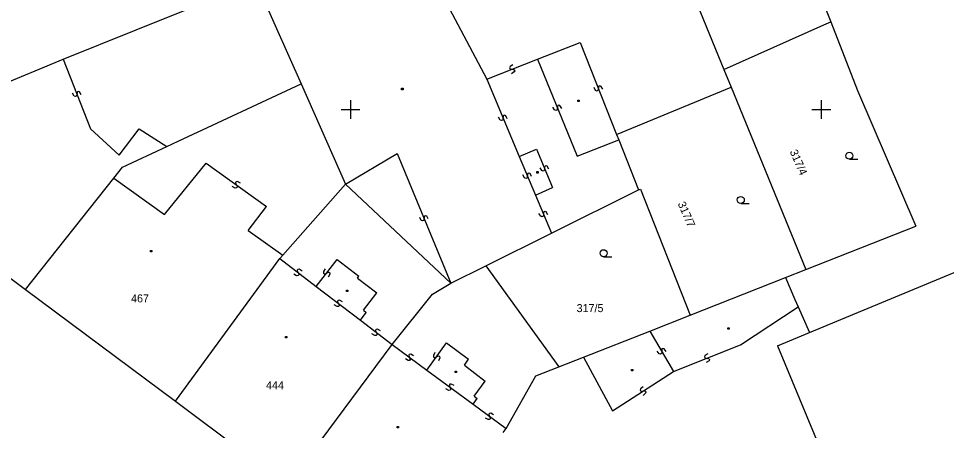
# Model space of a CAD drawing. Extents: x -492379 to -491966, y -1126153 to -1125860.
# Drawn here: x -492201.2 to -492142, y -1125920.5 to -1125894.2 of the extents above; entities that cross this region are included whole.
import ezdxf

# ---------------------------------------------------------------- set-up
doc = ezdxf.new("R2010")
doc.units = 0
doc.layers.add('katastrální mapa', color=7, linetype='Continuous')
doc.layers.add('síť', color=7, linetype='Continuous')

msp = doc.modelspace()

# ---------------------------------------------------------------- linework, layer by layer
at = {"layer": 'katastrální mapa'}
for p, q in [((-492176.64, -1125888.01), (-492171.32, -1125898.08)), ((-492150.75, -1125914.23), (-492091.06, -1125889.38)), ((-492150.62, -1125891.29), (-492149.4, -1125894.41)), ((-492193.65, -1125894.92), (-492186.04, -1125891.85)), ((-492186.04, -1125891.85), (-492183.14, -1125898.37)), ((-492158.08, -1125892.87), (-492156.21, -1125897.45)), ((-492156.21, -1125897.45), (-492149.83, -1125894.6)), ((-492149.83, -1125894.6), (-492149.4, -1125894.41)), ((-492149.4, -1125894.41), (-492147.69, -1125898.79)), ((-492198.3, -1125896.79), (-492193.65, -1125894.92)), ((-492168.08, -1125896.8), (-492165.36, -1125895.73)), ((-492165.36, -1125895.73), (-492163.05, -1125901.59)), ((-492209.37, -1125901.37), (-492198.3, -1125896.79)), ((-492198.3, -1125896.79), (-492196.56, -1125901.24)), ((-492171.32, -1125898.08), (-492168.08, -1125896.8)), ((-492169.83, -1125897.27), (-492169.87, -1125897.34)), ((-492169.65, -1125897.16), (-492169.83, -1125897.27)), ((-492168.08, -1125896.8), (-492165.56, -1125902.99)), ((-492169.87, -1125897.34), (-492169.84, -1125897.4)), ((-492169.84, -1125897.4), (-492169.77, -1125897.43)), ((-492169.77, -1125897.43), (-492169.63, -1125897.45)), ((-492169.57, -1125897.61), (-492169.75, -1125897.72)), ((-492169.63, -1125897.45), (-492169.56, -1125897.48)), ((-492169.53, -1125897.54), (-492169.57, -1125897.61)), ((-492169.56, -1125897.48), (-492169.53, -1125897.54)), ((-492156.21, -1125897.45), (-492155.74, -1125898.59)), ((-492190.98, -1125902.03), (-492183.14, -1125898.37)), ((-492183.14, -1125898.37), (-492180.31, -1125904.76)), ((-492171.32, -1125898.08), (-492169.25, -1125903)), ((-492197.6, -1125899.15), (-492197.71, -1125898.96)), ((-492197.42, -1125898.95), (-492197.44, -1125899.08)), ((-492197.39, -1125898.87), (-492197.42, -1125898.95)), ((-492197.33, -1125898.85), (-492197.39, -1125898.87)), ((-492197.26, -1125898.88), (-492197.33, -1125898.85)), ((-492197.15, -1125899.07), (-492197.26, -1125898.88)), ((-492176.74, -1125898.65), (-492176.65, -1125898.65)), ((-492176.74, -1125898.74), (-492176.74, -1125898.65)), ((-492176.65, -1125898.74), (-492176.74, -1125898.74)), ((-492176.65, -1125898.65), (-492176.65, -1125898.74)), ((-492164.38, -1125898.79), (-492164.48, -1125898.61)), ((-492164.3, -1125898.83), (-492164.38, -1125898.79)), ((-492164.24, -1125898.8), (-492164.3, -1125898.83)), ((-492164.21, -1125898.73), (-492164.24, -1125898.8)), ((-492164.2, -1125898.59), (-492164.21, -1125898.73)), ((-492164.17, -1125898.52), (-492164.2, -1125898.59)), ((-492164.11, -1125898.49), (-492164.17, -1125898.52)), ((-492164.03, -1125898.53), (-492164.11, -1125898.49)), ((-492163.93, -1125898.71), (-492164.03, -1125898.53)), ((-492163.05, -1125901.59), (-492155.74, -1125898.59)), ((-492155.74, -1125898.59), (-492150.99, -1125910.22)), ((-492147.69, -1125898.79), (-492143.97, -1125907.45)), ((-492197.53, -1125899.18), (-492197.6, -1125899.15)), ((-492197.47, -1125899.16), (-492197.53, -1125899.18)), ((-492197.44, -1125899.08), (-492197.47, -1125899.16)), ((-492165.52, -1125899.41), (-492165.43, -1125899.41)), ((-492165.52, -1125899.5), (-492165.52, -1125899.41)), ((-492165.43, -1125899.5), (-492165.52, -1125899.5)), ((-492165.43, -1125899.41), (-492165.43, -1125899.5)), ((-492166.99, -1125900.03), (-492167.1, -1125899.85)), ((-492166.91, -1125900.06), (-492166.99, -1125900.03)), ((-492166.86, -1125900.04), (-492166.91, -1125900.06)), ((-492166.83, -1125899.96), (-492166.86, -1125900.04)), ((-492166.81, -1125899.83), (-492166.83, -1125899.96)), ((-492166.78, -1125899.75), (-492166.81, -1125899.83)), ((-492166.73, -1125899.73), (-492166.78, -1125899.75)), ((-492166.65, -1125899.76), (-492166.73, -1125899.73)), ((-492166.54, -1125899.94), (-492166.65, -1125899.76)), ((-492170.46, -1125900.68), (-492170.56, -1125900.49)), ((-492170.38, -1125900.71), (-492170.46, -1125900.68)), ((-492170.32, -1125900.69), (-492170.38, -1125900.71)), ((-492170.29, -1125900.61), (-492170.32, -1125900.69)), ((-492170.28, -1125900.47), (-492170.29, -1125900.61)), ((-492170.25, -1125900.39), (-492170.28, -1125900.47)), ((-492170.19, -1125900.37), (-492170.25, -1125900.39)), ((-492170.11, -1125900.4), (-492170.19, -1125900.37)), ((-492170.01, -1125900.59), (-492170.11, -1125900.4)), ((-492196.56, -1125901.24), (-492194.74, -1125902.92)), ((-492194.74, -1125902.92), (-492193.47, -1125901.24)), ((-492193.47, -1125901.24), (-492191.7, -1125902.37)), ((-492165.56, -1125902.99), (-492162.91, -1125901.94)), ((-492163.05, -1125901.59), (-492162.91, -1125901.94)), ((-492162.91, -1125901.94), (-492161.64, -1125905.14)), ((-492194.52, -1125903.69), (-492191.7, -1125902.37)), ((-492191.7, -1125902.37), (-492190.98, -1125902.03)), ((-492169.25, -1125903), (-492168.15, -1125902.54)), ((-492168.15, -1125902.54), (-492167.12, -1125904.99)), ((-492180.31, -1125904.76), (-492177.02, -1125902.81)), ((-492177.02, -1125902.81), (-492173.61, -1125911.08)), ((-492169.25, -1125903), (-492168.22, -1125905.46)), ((-492148.21, -1125903.18), (-492147.68, -1125903.18)), ((-492195.08, -1125904.39), (-492194.52, -1125903.69)), ((-492191.86, -1125906.71), (-492189.19, -1125903.43)), ((-492189.19, -1125903.43), (-492185.36, -1125906.19)), ((-492167.81, -1125903.9), (-492167.91, -1125903.72)), ((-492167.63, -1125903.7), (-492167.64, -1125903.83)), ((-492167.6, -1125903.62), (-492167.63, -1125903.7)), ((-492167.54, -1125903.6), (-492167.6, -1125903.62)), ((-492167.46, -1125903.63), (-492167.54, -1125903.6)), ((-492167.36, -1125903.81), (-492167.46, -1125903.63)), ((-492168.91, -1125904.37), (-492169.01, -1125904.18)), ((-492168.74, -1125904.3), (-492168.77, -1125904.38)), ((-492168.73, -1125904.16), (-492168.74, -1125904.3)), ((-492168.7, -1125904.08), (-492168.73, -1125904.16)), ((-492168.64, -1125904.06), (-492168.7, -1125904.08)), ((-492168.56, -1125904.09), (-492168.64, -1125904.06)), ((-492168.46, -1125904.28), (-492168.56, -1125904.09)), ((-492168.13, -1125903.97), (-492168.04, -1125903.97)), ((-492168.13, -1125904.06), (-492168.13, -1125903.97)), ((-492168.04, -1125904.06), (-492168.13, -1125904.06)), ((-492168.04, -1125903.97), (-492168.04, -1125904.06)), ((-492167.73, -1125903.93), (-492167.81, -1125903.9)), ((-492167.67, -1125903.91), (-492167.73, -1125903.93)), ((-492167.64, -1125903.83), (-492167.67, -1125903.91)), ((-492209.77, -1125904.73), (-492200.7, -1125911.49)), ((-492200.7, -1125911.49), (-492195.08, -1125904.39)), ((-492195.08, -1125904.39), (-492191.86, -1125906.71)), ((-492187.35, -1125905.02), (-492187.54, -1125904.92)), ((-492187.28, -1125904.62), (-492187.32, -1125904.67)), ((-492187.32, -1125904.67), (-492187.31, -1125904.75)), ((-492187.31, -1125904.75), (-492187.24, -1125904.87)), ((-492187.2, -1125904.6), (-492187.28, -1125904.62)), ((-492187.23, -1125904.95), (-492187.27, -1125905)), ((-492187.24, -1125904.87), (-492187.23, -1125904.95)), ((-492187.01, -1125904.7), (-492187.2, -1125904.6)), ((-492184.31, -1125909.3), (-492180.31, -1125904.76)), ((-492180.31, -1125904.76), (-492173.61, -1125911.08)), ((-492168.83, -1125904.4), (-492168.91, -1125904.37)), ((-492168.77, -1125904.38), (-492168.83, -1125904.4)), ((-492187.27, -1125905), (-492187.35, -1125905.02)), ((-492168.22, -1125905.46), (-492167.12, -1125904.99)), ((-492168.22, -1125905.46), (-492167.2, -1125907.9)), ((-492167.2, -1125907.9), (-492161.64, -1125905.14)), ((-492161.64, -1125905.14), (-492161.53, -1125905.08)), ((-492161.53, -1125905.08), (-492158.36, -1125913.13)), ((-492155.13, -1125906), (-492154.6, -1125906)), ((-492186.51, -1125907.72), (-492185.36, -1125906.19)), ((-492167.88, -1125906.82), (-492167.99, -1125906.63)), ((-492167.67, -1125906.53), (-492167.71, -1125906.61)), ((-492167.71, -1125906.61), (-492167.71, -1125906.75)), ((-492167.62, -1125906.51), (-492167.67, -1125906.53)), ((-492167.54, -1125906.54), (-492167.62, -1125906.51)), ((-492167.43, -1125906.73), (-492167.54, -1125906.54)), ((-492175.49, -1125907.08), (-492175.59, -1125906.9)), ((-492175.41, -1125907.11), (-492175.49, -1125907.08)), ((-492175.35, -1125907.09), (-492175.41, -1125907.11)), ((-492175.32, -1125907.01), (-492175.35, -1125907.09)), ((-492175.31, -1125906.88), (-492175.32, -1125907.01)), ((-492175.28, -1125906.8), (-492175.31, -1125906.88)), ((-492175.22, -1125906.78), (-492175.28, -1125906.8)), ((-492175.14, -1125906.81), (-492175.22, -1125906.78)), ((-492175.04, -1125906.99), (-492175.14, -1125906.81)), ((-492167.8, -1125906.85), (-492167.88, -1125906.82)), ((-492167.75, -1125906.83), (-492167.8, -1125906.85)), ((-492167.71, -1125906.75), (-492167.75, -1125906.83)), ((-492186.51, -1125907.72), (-492184.31, -1125909.3)), ((-492171.37, -1125909.97), (-492167.2, -1125907.9)), ((-492150.99, -1125910.22), (-492143.97, -1125907.45)), ((-492192.75, -1125908.99), (-492192.66, -1125908.99)), ((-492192.75, -1125909.08), (-492192.75, -1125908.99)), ((-492192.66, -1125909.08), (-492192.75, -1125909.08)), ((-492192.66, -1125908.99), (-492192.66, -1125909.08)), ((-492191.15, -1125918.62), (-492184.51, -1125909.51)), ((-492184.51, -1125909.51), (-492184.31, -1125909.3)), ((-492184.51, -1125909.51), (-492182.18, -1125911.3)), ((-492182.18, -1125911.3), (-492180.85, -1125909.57)), ((-492180.85, -1125909.57), (-492179.46, -1125910.64)), ((-492163.87, -1125909.4), (-492163.34, -1125909.4)), ((-492183.35, -1125910.21), (-492183.39, -1125910.26)), ((-492183.39, -1125910.26), (-492183.37, -1125910.34)), ((-492183.26, -1125910.2), (-492183.35, -1125910.21)), ((-492183.08, -1125910.31), (-492183.26, -1125910.2)), ((-492181.61, -1125910.17), (-492181.72, -1125910.35)), ((-492173.61, -1125911.08), (-492171.37, -1125909.97)), ((-492171.37, -1125909.97), (-492166.72, -1125916.42)), ((-492152.29, -1125910.73), (-492150.99, -1125910.22)), ((-492183.43, -1125910.61), (-492183.61, -1125910.5)), ((-492183.34, -1125910.6), (-492183.43, -1125910.61)), ((-492183.37, -1125910.34), (-492183.32, -1125910.47)), ((-492183.3, -1125910.55), (-492183.34, -1125910.6)), ((-492183.32, -1125910.47), (-492183.3, -1125910.55)), ((-492181.72, -1125910.35), (-492181.71, -1125910.44)), ((-492181.71, -1125910.44), (-492181.66, -1125910.48)), ((-492181.66, -1125910.48), (-492181.58, -1125910.46)), ((-492181.58, -1125910.46), (-492181.45, -1125910.41)), ((-492181.45, -1125910.41), (-492181.37, -1125910.39)), ((-492181.31, -1125910.52), (-492181.42, -1125910.7)), ((-492181.37, -1125910.39), (-492181.32, -1125910.43)), ((-492181.32, -1125910.43), (-492181.31, -1125910.52)), ((-492179.56, -1125910.76), (-492179.46, -1125910.64)), ((-492179.56, -1125910.76), (-492178.32, -1125911.71)), ((-492158.36, -1125913.13), (-492152.29, -1125910.73)), ((-492152.29, -1125910.73), (-492151.68, -1125912.13)), ((-492182.18, -1125911.3), (-492179.37, -1125913.45)), ((-492174.78, -1125911.79), (-492173.61, -1125911.08)), ((-492200.7, -1125911.49), (-492191.15, -1125918.62)), ((-492180.25, -1125911.52), (-492180.16, -1125911.52)), ((-492180.25, -1125911.61), (-492180.25, -1125911.52)), ((-492180.16, -1125911.61), (-492180.25, -1125911.61)), ((-492180.16, -1125911.52), (-492180.16, -1125911.61)), ((-492179.17, -1125912.81), (-492178.32, -1125911.71)), ((-492177.35, -1125915), (-492174.78, -1125911.79)), ((-492180.85, -1125912.58), (-492181.04, -1125912.47)), ((-492180.77, -1125912.57), (-492180.85, -1125912.58)), ((-492180.78, -1125912.18), (-492180.82, -1125912.23)), ((-492180.82, -1125912.23), (-492180.8, -1125912.31)), ((-492180.8, -1125912.31), (-492180.75, -1125912.44)), ((-492180.7, -1125912.17), (-492180.78, -1125912.18)), ((-492180.73, -1125912.52), (-492180.77, -1125912.57)), ((-492180.75, -1125912.44), (-492180.73, -1125912.52)), ((-492180.51, -1125912.28), (-492180.7, -1125912.17)), ((-492155.15, -1125915.02), (-492151.47, -1125912.59)), ((-492151.68, -1125912.13), (-492151.47, -1125912.59)), ((-492151.47, -1125912.59), (-492150.75, -1125914.23)), ((-492179.37, -1125913.45), (-492178.99, -1125912.95)), ((-492179.17, -1125912.81), (-492178.99, -1125912.95)), ((-492160.92, -1125914.14), (-492158.36, -1125913.13)), ((-492179.37, -1125913.45), (-492177.35, -1125915)), ((-492178.44, -1125914.43), (-492178.63, -1125914.32)), ((-492178.36, -1125914.03), (-492178.4, -1125914.08)), ((-492178.4, -1125914.08), (-492178.39, -1125914.16)), ((-492178.39, -1125914.16), (-492178.33, -1125914.29)), ((-492178.28, -1125914.02), (-492178.36, -1125914.03)), ((-492178.32, -1125914.37), (-492178.36, -1125914.42)), ((-492178.33, -1125914.29), (-492178.32, -1125914.37)), ((-492178.09, -1125914.13), (-492178.28, -1125914.02)), ((-492165.16, -1125915.81), (-492160.92, -1125914.14)), ((-492160.92, -1125914.14), (-492159.42, -1125916.72)), ((-492155.95, -1125913.93), (-492155.86, -1125913.93)), ((-492155.95, -1125914.02), (-492155.95, -1125913.93)), ((-492155.86, -1125914.02), (-492155.95, -1125914.02)), ((-492155.86, -1125913.93), (-492155.86, -1125914.02)), ((-492152.78, -1125915.08), (-492150.75, -1125914.23)), ((-492184.14, -1125914.49), (-492184.05, -1125914.49)), ((-492184.14, -1125914.58), (-492184.14, -1125914.49)), ((-492184.05, -1125914.58), (-492184.14, -1125914.58)), ((-492184.05, -1125914.49), (-492184.05, -1125914.58)), ((-492183.99, -1125923.95), (-492177.35, -1125915)), ((-492178.36, -1125914.42), (-492178.44, -1125914.43)), ((-492177.35, -1125915), (-492175.13, -1125916.64)), ((-492175.13, -1125916.64), (-492173.89, -1125914.9)), ((-492173.89, -1125914.9), (-492172.48, -1125915.93)), ((-492174.62, -1125915.51), (-492174.72, -1125915.7)), ((-492160.32, -1125915.59), (-492160.45, -1125915.42)), ((-492160.24, -1125915.61), (-492160.32, -1125915.59)), ((-492160.19, -1125915.58), (-492160.24, -1125915.61)), ((-492160.17, -1125915.5), (-492160.19, -1125915.58)), ((-492160.15, -1125915.28), (-492160.17, -1125915.36)), ((-492160.17, -1125915.36), (-492160.17, -1125915.5)), ((-492160.1, -1125915.25), (-492160.15, -1125915.28)), ((-492160.02, -1125915.27), (-492160.1, -1125915.25)), ((-492159.89, -1125915.44), (-492160.02, -1125915.27)), ((-492159.42, -1125916.72), (-492155.15, -1125915.02)), ((-492157.23, -1125915.59), (-492157.42, -1125915.7)), ((-492152.78, -1125915.08), (-492149.61, -1125922.76)), ((-492176.32, -1125916.02), (-492176.5, -1125915.92)), ((-492176.23, -1125916.01), (-492176.32, -1125916.02)), ((-492176.25, -1125915.63), (-492176.28, -1125915.68)), ((-492176.28, -1125915.68), (-492176.27, -1125915.76)), ((-492176.27, -1125915.76), (-492176.21, -1125915.88)), ((-492176.16, -1125915.62), (-492176.25, -1125915.63)), ((-492176.2, -1125915.96), (-492176.23, -1125916.01)), ((-492176.21, -1125915.88), (-492176.2, -1125915.96)), ((-492175.98, -1125915.72), (-492176.16, -1125915.62)), ((-492174.72, -1125915.7), (-492174.7, -1125915.78)), ((-492174.7, -1125915.78), (-492174.65, -1125915.82)), ((-492174.65, -1125915.82), (-492174.57, -1125915.8)), ((-492174.57, -1125915.8), (-492174.45, -1125915.74)), ((-492174.45, -1125915.74), (-492174.37, -1125915.72)), ((-492174.3, -1125915.84), (-492174.4, -1125916.03)), ((-492174.37, -1125915.72), (-492174.32, -1125915.76)), ((-492174.32, -1125915.76), (-492174.3, -1125915.84)), ((-492172.73, -1125916.32), (-492172.48, -1125915.93)), ((-492166.72, -1125916.42), (-492165.16, -1125915.81)), ((-492165.16, -1125915.81), (-492163.3, -1125919.22)), ((-492157.42, -1125915.7), (-492157.45, -1125915.78)), ((-492157.45, -1125915.78), (-492157.43, -1125915.83)), ((-492157.43, -1125915.83), (-492157.35, -1125915.86)), ((-492157.35, -1125915.86), (-492157.22, -1125915.88)), ((-492157.15, -1125916.04), (-492157.34, -1125916.15)), ((-492157.22, -1125915.88), (-492157.14, -1125915.91)), ((-492157.12, -1125915.96), (-492157.15, -1125916.04)), ((-492157.14, -1125915.91), (-492157.12, -1125915.96)), ((-492175.13, -1125916.64), (-492172.19, -1125918.81)), ((-492173.33, -1125916.69), (-492173.24, -1125916.69)), ((-492173.33, -1125916.78), (-492173.33, -1125916.69)), ((-492173.24, -1125916.78), (-492173.33, -1125916.78)), ((-492173.24, -1125916.69), (-492173.24, -1125916.78)), ((-492172.73, -1125916.32), (-492171.41, -1125917.33)), ((-492168.18, -1125917), (-492166.72, -1125916.42)), ((-492163.3, -1125919.22), (-492159.42, -1125916.72)), ((-492162.1, -1125916.59), (-492162.01, -1125916.59)), ((-492162.1, -1125916.68), (-492162.1, -1125916.59)), ((-492162.01, -1125916.68), (-492162.1, -1125916.68)), ((-492162.01, -1125916.59), (-492162.01, -1125916.68)), ((-492172.12, -1125918.29), (-492171.41, -1125917.33)), ((-492170.09, -1125920.36), (-492168.18, -1125917)), ((-492173.74, -1125917.93), (-492173.92, -1125917.83)), ((-492173.65, -1125917.92), (-492173.74, -1125917.93)), ((-492173.67, -1125917.53), (-492173.7, -1125917.58)), ((-492173.7, -1125917.58), (-492173.69, -1125917.67)), ((-492173.69, -1125917.67), (-492173.63, -1125917.78)), ((-492173.58, -1125917.52), (-492173.67, -1125917.53)), ((-492173.62, -1125917.87), (-492173.65, -1125917.92)), ((-492173.63, -1125917.78), (-492173.62, -1125917.87)), ((-492173.4, -1125917.62), (-492173.58, -1125917.52)), ((-492161.52, -1125917.83), (-492161.54, -1125917.91)), ((-492161.54, -1125917.91), (-492161.51, -1125917.96)), ((-492161.36, -1125917.69), (-492161.52, -1125917.83)), ((-492161.51, -1125917.96), (-492161.43, -1125917.98)), ((-492161.43, -1125917.98), (-492161.29, -1125917.96)), ((-492161.29, -1125917.96), (-492161.21, -1125917.98)), ((-492172.19, -1125918.81), (-492171.92, -1125918.44)), ((-492172.12, -1125918.29), (-492171.92, -1125918.44)), ((-492161.2, -1125918.11), (-492161.36, -1125918.25)), ((-492161.21, -1125917.98), (-492161.18, -1125918.03)), ((-492161.18, -1125918.03), (-492161.2, -1125918.11)), ((-492191.15, -1125918.62), (-492183.99, -1125923.95)), ((-492172.19, -1125918.81), (-492170.09, -1125920.36)), ((-492171.22, -1125919.79), (-492171.4, -1125919.69)), ((-492171.15, -1125919.39), (-492171.18, -1125919.44)), ((-492171.18, -1125919.44), (-492171.17, -1125919.53)), ((-492171.17, -1125919.53), (-492171.11, -1125919.64)), ((-492171.06, -1125919.38), (-492171.15, -1125919.39)), ((-492171.1, -1125919.73), (-492171.13, -1125919.78)), ((-492171.11, -1125919.64), (-492171.1, -1125919.73)), ((-492170.88, -1125919.48), (-492171.06, -1125919.38)), ((-492177.02, -1125920.23), (-492176.93, -1125920.23)), ((-492177.02, -1125920.32), (-492177.02, -1125920.23)), ((-492176.93, -1125920.32), (-492177.02, -1125920.32)), ((-492176.93, -1125920.23), (-492176.93, -1125920.32)), ((-492171.13, -1125919.78), (-492171.22, -1125919.79)), ((-492170.27, -1125920.6), (-492170.09, -1125920.36))]:
    msp.add_line(p, q, dxfattribs=at)
for centre in [(-492148.21, -1125902.955), (-492155.13, -1125905.775), (-492163.87, -1125909.175)]:
    msp.add_circle(centre, 0.225, dxfattribs=at)
at = {"layer": 'síť'}
for p, q in [((-492180, -1125899.4), (-492180, -1125900.6)), ((-492150, -1125899.4), (-492150, -1125900.6)), ((-492180.6, -1125900), (-492179.4, -1125900)), ((-492150.6, -1125900), (-492149.4, -1125900))]:
    msp.add_line(p, q, dxfattribs=at)

# ---------------------------------------------------------------- texts
at = {"layer": 'katastrální mapa'}
for s, p in [('317/4', (-492152.02, -1125902.69)), ('317/7', (-492159.16, -1125906.01))]:
    msp.add_text(s, height=0.51, rotation=293.526, dxfattribs=at).set_placement(p)
for s, p in [('467', (-492193.98, -1125912.31)), ('317/5', (-492165.59, -1125912.93)), ('444', (-492185.38, -1125917.85))]:
    msp.add_text(s, height=0.51, dxfattribs=at).set_placement(p)

doc.saveas('drawing.dxf')
